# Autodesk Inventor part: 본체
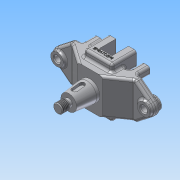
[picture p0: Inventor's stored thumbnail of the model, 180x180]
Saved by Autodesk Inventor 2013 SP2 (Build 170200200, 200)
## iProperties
Created: 2025-07
Part Number: 본체
Material: 알루미늄 6061
Document SubType Name: Modeling
Designer: a
Density: 2.71 g/cm^3
Mass: 328.836 g
Surface Area: 260.948 cm^2
Volume: 121.342 cm^3
Author: a
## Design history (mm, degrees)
sketch "스케치1"
  geometry: L1 (0, -23)-(41.804, -23); L2 (41.804, -23)-(61.157, -7.88); L3 (61.157, 7.88)-(41.804, 23); L4 (41.804, 23)-(0, 23); L5 (0, 23)-(0, -23); L6 (55, 0)-(0, 0); L7 (0, -23)-(-41.804, -23); L8 (-41.804, -23)-(-61.157, -7.88); L9 (-61.157, 7.88)-(-41.804, 23); L10 (-41.804, 23)-(0, 23); L11 (-55, 0)-(0, 0); A1 r 10 centre (55, 0) between (61.157, -7.88) and (61.157, 7.88); A2 r 10 centre (-55, 0) between (-61.157, -7.88) and (-61.157, 7.88); 1 further point
  constraints: 22 end point, 5 symmetric about line, 4 point on circle, 2 centre point, 2 perpendicular, 2 tangent, 1 coincident, 1 horizontal, 1 midpoint, 1 parallel, 1 other
  dimensions: "d0" = 46 distance between parallel lines of L4 L1; "d2" = 23 distance from line of L1 L6.end; "d3" = 20 diameter of A1; "d4" = 38 deg angle of L2 L6; "d5" = 38 deg angle of L3 L6; "d6" = 55 distance from line of L5 L6.start
extrude "돌출1" new body sketch "스케치1" stored distance "d7" = 9; taper "d8" = 0 deg
sketch "스케치2"
  geometry: L1 (-41.804, -23)-(41.804, -23) reference; L2 (-35, -13)-(-25, -13); L3 (-25, -13)-(-25, -23); L4 (-25, -23)-(-35, -23); L5 (-35, -23)-(-35, -13); L6 (-35, -13)-(-25, -23); L7 (-25, -13)-(-35, -23); L8 (25, -13)-(35, -13); L9 (35, -13)-(35, -23); L10 (35, -23)-(25, -23); L11 (25, -23)-(25, -13); L12 (25, -13)-(35, -23); L13 (35, -13)-(25, -23); L14 (-52.738, 0)-(55, 0); L15 (-25, 23)-(-35, 23); L16 (-25, 13)-(-25, 23); L17 (-35, 13)-(-25, 13); L18 (-35, 23)-(-35, 13); L19 (35, 23)-(25, 23); L20 (25, 23)-(25, 13); L21 (25, 13)-(35, 13); L22 (35, 13)-(35, 23); L23 (-18, 32)-(18, 32); L24 (18, 32)-(18, 13); L25 (18, 13)-(-18, 13); L26 (-18, 13)-(-18, 32); L27 (-18, -13)-(18, -13); L28 (18, -13)-(18, -32); L29 (18, -32)-(-18, -32); L30 (-18, -32)-(-18, -13); A1 r 10 centre (55, 0) between (61.157, -7.88) and (61.157, 7.88) reference; 5 further points
  constraints: 58 end point, 8 parallel, 8 symmetric about line, 6 midpoint, 5 perpendicular, 4 horizontal, 2 point on line
  dimensions: "d9" = 10 distance of L3.end L4.end; "d10" = 10 distance of L2.end L3.end; "d11" = 10 distance of L9.end L10.end; "d12" = 10 distance of L8.end L9.end; "d13" = 60 distance of point (30, -18) point (-30, -18); "d14" = 30 horizontal distance of point (0, 0) point (-30, -18); "d15" = 36 distance of L23.start L23.end; "d16" = 36 distance of L28.end L29.end; "d17" = 18 distance from line of L26 point (0, 0); "d18" = 18 distance from line of L30 point (0, 0); "d19" = 64 distance between parallel lines of L29 L23; "d20" = 32 distance from line of L29 point (0, 0); "d21" = 26 distance between parallel lines of L27 L25; "d22" = 13 distance from line of point (0, 0) L25
extrude "돌출2" join sketch "스케치2" distance "d24" = 16; taper "d25" = 0 deg
extrude "돌출3" join sketch "스케치2" distance "d26" = 16; taper "d28" = 0 deg; dims "d27" = 15, "d29" = 0
sketch "스케치3"
  geometry: L1 (-65, 4.5)-(65, 4.5) reference; L2 (65, 4.5)-(65, -4.5) reference; L3 (65, -4.5)-(-65, -4.5) reference; L4 (-65, -4.5)-(-65, 4.5) reference; L5 (-38.85, -4.5)-(-16, -20.5); L6 (-16, -20.5)-(16, -20.5); L7 (16, -20.5)-(38.85, -4.5); L8 (38.85, -4.5)-(-38.85, -4.5); L9 (25, 20.5)-(35, 20.5) reference; 1 further point
  constraints: 8 end point, 2 point on line, 1 perpendicular
  dimensions: "d30" = 32 distance of L5.end L6.end; "d32" = 16 horizontal distance of L5.end point (0, 0); "d33" = 35 deg angle of L6 L5; "d34" = 35 deg angle of L6 L7; "d35" = 41 distance between parallel lines of L9 L6
extrude "돌출4" join sketch "스케치3" stored distance "d36" = 46; taper "d37" = 0 deg
sketch "스케치4"
  geometry: L1 (0, 0)-(36, 0) reference; L2 (10, 21)-(26, 21); L3 (26, 21)-(26, -21); L4 (26, -21)-(10, -21); L5 (10, -21)-(10, 21); L6 (10, 21)-(26, -21); L7 (26, 21)-(10, -21); 2 further points
  constraints: 12 end point, 3 midpoint, 2 parallel, 1 horizontal, 1 perpendicular
  dimensions: "d38" = 16 distance of L3.end L4.end; "d39" = 42 distance of L2.end L3.end
extrude "돌출5" cut sketch "스케치4" distance "d40" = 184.75; taper "d41" = 0 deg
sketch "스케치5"
  geometry: L1 (38.85, -4.5)-(16, -20.5) reference; L2 (16, -20.5)-(-16, -20.5) reference; L3 (-16, -20.5)-(-38.85, -4.5) reference; L4 (-38.85, -4.5)-(-65, -4.5) reference; L5 (-65, -4.5)-(-65, 4.5) reference; L6 (-65, 4.5)-(-8, 4.5) reference; L7 (-8, 4.5)-(-8, -0.5) reference; L8 (-8, -0.5)-(8, -0.5) reference; L9 (8, -0.5)-(8, 4.5) reference; L10 (8, 4.5)-(65, 4.5) reference; L11 (65, 4.5)-(65, -4.5) reference; L12 (65, -4.5)-(38.85, -4.5) reference; L13 (-12.5, -20.5)-(-12.5, -24.5); L14 (-12.5, -24.5)-(-10, -47.5); L15 (-10, -47.5)-(0, -47.5); L16 (0, -47.5)-(0, -20.5); L17 (0, -20.5)-(-12.5, -20.5); 1 further point
  constraints: 10 end point, 3 perpendicular, 1 midpoint, 1 point on line
  dimensions: "d42" = 4 distance of L13.start L13.end; "d44" = 23 distance from line of L15 L13.end; "d45" = 25 diameter of L13 L16; "d46" = 20 diameter of L14.end L16
revolve "회전1" sketch "스케치5" stored, may be unused: angle "d47" = 90 deg
sketch "스케치6"
  geometry: L1 (38.85, -4.5)-(16, -20.5) reference; L2 (16, -20.5)-(12.5, -20.5) reference; L3 (12.5, -20.5)-(12.5, -24.5) reference; L4 (12.5, -24.5)-(10, -47.5) reference; L5 (10, -47.5)-(-10, -47.5) reference; L6 (-10, -47.5)-(-12.5, -24.5) reference; L7 (-12.5, -24.5)-(-12.5, -20.5) reference; L8 (-12.5, -20.5)-(-16, -20.5) reference; L9 (-16, -20.5)-(-38.85, -4.5) reference; L10 (-38.85, -4.5)-(-65, -4.5) reference; L11 (-65, -4.5)-(-65, 4.5) reference; L12 (-65, 4.5)-(-8, 4.5) reference; L13 (-8, 4.5)-(-8, -0.5) reference; L14 (-8, -0.5)-(8, -0.5) reference; L15 (8, -0.5)-(8, 4.5) reference; L16 (8, 4.5)-(65, 4.5) reference; L17 (65, 4.5)-(65, -4.5) reference; L18 (65, -4.5)-(38.85, -4.5) reference; L19 (-4.7, -47.5)-(-4.7, -50.5); L20 (-4.7, -50.5)-(-6, -52.752); L21 (-6, -52.752)-(-6, -61.5); L22 (-6, -61.5)-(0, -61.5); L23 (0, -61.5)-(0, -47.5); L24 (0, -47.5)-(-4.7, -47.5); 1 further point
  constraints: 12 end point, 2 perpendicular, 1 collinear, 1 midpoint, 1 parallel, 1 point on line
  dimensions: "d48" = 3 distance of L19.start L19.end; "d50" = 30 deg angle of L19 L20; "d52" = 41 distance between parallel lines of L8 L22; "d53" = 9.4 diameter of L19 L23; "d54" = 12 diameter of L21 L23
revolve "회전2" sketch "스케치6" stored, may be unused: angle "d55" = 90 deg
feature "스레드1" dims "d56" = 10, "d57" = 0
chamfer "모따기1" distance "d58" = 1; stored, may be unused: second distance "d59" = 2, angle "d60" = 45 deg
sketch "스케치7"
  geometry: L1 (8, 13)-(8, -13) reference; L2 (8, -13)-(18, -13) reference; L3 (18, -13)-(18, -23) reference; L4 (18, -23)-(25, -23) reference; L5 (25, -23)-(25, -13) reference; L6 (25, -13)-(35, -13) reference; L7 (35, -13)-(35, -23) reference; L8 (35, -23)-(41.804, -23) reference; L9 (41.804, -23)-(61.157, -7.88) reference; L10 (61.157, 7.88)-(41.804, 23) reference; L11 (41.804, 23)-(35, 23) reference; L12 (35, 23)-(35, 13) reference; L13 (35, 13)-(25, 13) reference; L14 (25, 13)-(25, 23) reference; L15 (25, 23)-(18, 23) reference; L16 (18, 23)-(18, 13) reference; L17 (18, 13)-(8, 13) reference; L18 (-8, -13)-(-8, 13) reference; L19 (-8, 13)-(-18, 13) reference; L20 (-18, 13)-(-18, 23) reference; L21 (-18, 23)-(-25, 23) reference; L22 (-25, 23)-(-25, 13) reference; L23 (-25, 13)-(-35, 13) reference; L24 (-35, 13)-(-35, 23) reference; L25 (-35, 23)-(-41.804, 23) reference; L26 (-41.804, 23)-(-61.157, 7.88) reference; L27 (-61.157, -7.88)-(-41.804, -23) reference; L28 (-41.804, -23)-(-35, -23) reference; L29 (-35, -23)-(-35, -13) reference; L30 (-35, -13)-(-25, -13) reference; L31 (-25, -13)-(-25, -23) reference; L32 (-25, -23)-(-18, -23) reference; L33 (-18, -23)-(-18, -13) reference; L34 (-18, -13)-(-8, -13) reference; C1 r 8 at (-55, 0); C2 r 8 at (55, 0); A1 r 10 centre (55, 0) between (61.157, -7.88) and (61.157, 7.88) reference; A2 r 10 centre (-55, 0) between (-61.157, 7.88) and (-61.157, -7.88) reference; 1 further point
  constraints: 2 centre point, 2 coincident
  dimensions: "d61" = 16 diameter of C1; "d62" = 16 diameter of C2
extrude "돌출6" join sketch "스케치7" distance "d63" = 3; taper "d64" = 0 deg
fillet "모깎기1" dims "d65" = 3
fillet "모깎기2" dims "d66" = 3
fillet "모깎기3" dims "d67" = 3
fillet "모깎기4" dims "d68" = 3
fillet "모깎기5" dims "d69" = 3
fillet "모깎기6" dims "d70" = 3
fillet "모깎기7" dims "d71" = 3
fillet "모깎기8" dims "d72" = 3
fillet "모깎기9" dims "d73" = 3
fillet "모깎기10" dims "d74" = 3
fillet "모깎기11" dims "d75" = 3
fillet "모깎기12" dims "d76" = 3
sketch "스케치8"
  geometry: A1 r 8 centre (-55, 0) between (-53.271, -7.811) and (-53.271, 7.811) reference; A2 r 8 centre (55, 0) between (53.271, -7.811) and (53.271, 7.811) reference; A3 r 8 centre (55, 0) between (53.271, 7.811) and (53.271, -7.811) reference; 1 further point
hole "구멍1" sketch "스케치8" at (-55, 0), (55, 0) diameter "d77" = 8; stored, may be unused: countersink angle "d81" = 90 deg, drill point angle "d83" = 118 deg; dims "d78" = 6, "d79" = 4, "d80" = 2, "d82" = 8
chamfer "모따기2" distance "d84" = 1; stored, may be unused: second distance "d85" = 2, angle "d86" = 45 deg
sketch "스케치9"
  geometry: L1 (-35, 20)-(-35, 16) reference; L2 (-25, 16)-(-25, 20) reference; L3 (-35, 18)-(-25, 18); 2 further points
  constraints: 3 midpoint, 2 end point
hole "구멍2" sketch "스케치9" at (-30, 18) diameter "d87" = 2.459; stored, may be unused: countersink angle "d91" = 90 deg, drill point angle "d93" = 118 deg; dims "d88" = 6, "d89" = 4, "d90" = 2, "d92" = 8
sketch "스케치10"
  geometry: 2 further points
  dimensions: "d94" = 13 horizontal distance of point (0, 0) point (-13, -18); "d95" = 18 vertical distance of point (0, 0) point (-13, -18)
hole "구멍3" sketch "스케치10" at (-13, -18) diameter "d96" = 2.459; stored, may be unused: countersink angle "d100" = 90 deg, drill point angle "d102" = 118 deg; dims "d97" = 6, "d98" = 4, "d99" = 2, "d101" = 8
sketch "스케치11"
  geometry: L1 (-61.5, 5)-(-60.5, 6) reference; L2 (-60.5, 6)-(-52.752, 6) reference; L3 (-52.752, 6)-(-50.5, 4.7) reference; L4 (-50.5, 4.7)-(-47.5, 4.7) reference; L5 (-47.5, 4.7)-(-47.5, 10) reference; L6 (-47.5, 10)-(-24.5, 12.5) reference; L7 (-24.5, 12.5)-(-20.5, 12.5) reference; L8 (-20.5, 12.5)-(-20.5, 23) reference; L9 (-20.5, 23)-(-13.5, 23) reference; L10 (-10.5, 26)-(-10.5, 29) reference; L11 (-7.5, 32)-(-0.5, 32) reference; L12 (-0.5, 32)-(-0.5, -32) reference; L13 (-0.5, -32)-(-7.5, -32) reference; L14 (-10.5, -29)-(-10.5, -26) reference; L15 (-13.5, -23)-(-20.5, -23) reference; L16 (-20.5, -23)-(-20.5, -12.5) reference; L17 (-20.5, -12.5)-(-24.5, -12.5) reference; L18 (-24.5, -12.5)-(-47.5, -10) reference; L19 (-47.5, -10)-(-47.5, -4.7) reference; L20 (-47.5, -4.7)-(-50.5, -4.7) reference; L21 (-50.5, -4.7)-(-52.752, -6) reference; L22 (-52.752, -6)-(-60.5, -6) reference; L23 (-60.5, -6)-(-61.5, -5) reference; L24 (-61.5, -5)-(-61.5, 5) reference; L25 (-24.5, 12.5)-(-47.5, 10); L26 (-47.5, 10)-(-47.068, 6.023); L27 (-43.523, 10.432)-(-27.617, 12.161); L28 (-27.617, 12.161)-(-27.185, 8.185); L29 (-27.185, 8.185)-(-43.091, 6.456); L30 (-43.091, 6.456)-(-43.523, 10.432); A1 r 3 centre (-13.5, 26) between (-13.5, 23) and (-10.5, 26) reference; A2 r 3 centre (-7.5, 29) between (-7.5, 32) and (-10.5, 29) reference; A3 r 3 centre (-7.5, -29) between (-10.5, -29) and (-7.5, -32) reference; A4 r 3 centre (-13.5, -26) between (-10.5, -26) and (-13.5, -23) reference; 1 further point
  constraints: 12 end point, 3 equal length, 1 perpendicular, 1 other
  dimensions: "d104" = 4 distance between parallel lines of L26 L30; "d105" = 16 distance between parallel lines of L30 L28
extrude "돌출7" cut sketch "스케치11" stored distance "d106" = 7; taper "d107" = 0 deg
fillet "모깎기13" dims "d108" = 3.5
sketch "스케치12"
  geometry: L1 (16, 0)-(0, 0) reference; L2 (-7, 21)-(0, 21) reference; 3 further points
  constraints: 1 midpoint, 1 vertical alignment, 1 other
  dimensions: "d109" = 24 distance from line of point (8, -3) L2
feature "엠보싱1" sketch "스케치12" dims "d110" = 0.5, "d111" = 0
node "솔리드1"
mirror "대칭1"
mirror "대칭2"
mirror "대칭3"
mirror "대칭4"
mirror "대칭5"
node "투영된 루프1"
node "투영된 루프2"
node "투영된 루프3"
node "절단 모서리 투영1"
node "절단 모서리 투영2"
node "절단 모서리 투영3"
node "절단 모서리 투영4"
